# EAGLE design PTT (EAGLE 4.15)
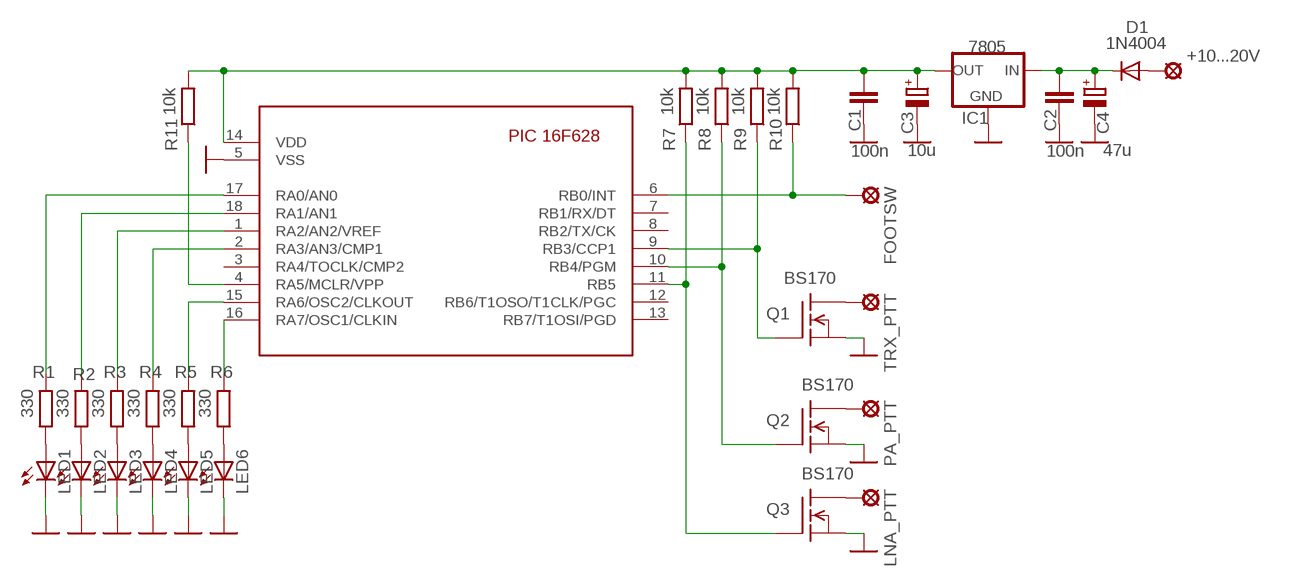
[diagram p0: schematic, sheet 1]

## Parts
+10...20V  MCS08  [MCS08]
C1  100n  C-EU050-025X075  [C050-025X075]
C2  100n  C-EU050-025X075  [C050-025X075]
C3  10u  CPOL-EUB45181C  [B45181C]
C4  47u  CPOL-EUB45181C  [B45181C]
D1  1N4004  [DO41-10]
FOOTSW  MCS08  [MCS08]
IC1  7805  78XXS  [78XXS]
LED1  LED3MM  [LED3MM]
LED2  LED3MM  [LED3MM]
LED3  LED3MM  [LED3MM]
LED4  LED3MM  [LED3MM]
LED5  LED3MM  [LED3MM]
LED6  LED3MM  [LED3MM]
LNA_PTT  MCS08  [MCS08]
PA_PTT  MCS08  [MCS08]
Q1  BS170  BSS296  [TO92]
Q2  BS170  BSS296  [TO92]
Q3  BS170  BSS296  [TO92]
R1  330  R-EU_0204/7  [0204/7]
R2  330  R-EU_0204/7  [0204/7]
R3  330  R-EU_0204/7  [0204/7]
R4  330  R-EU_0204/7  [0204/7]
R5  330  R-EU_0204/7  [0204/7]
R6  330  R-EU_0204/7  [0204/7]
R7  10k  R-EU_0204/7  [0204/7]
R8  10k  R-EU_0204/7  [0204/7]
R9  10k  R-EU_0204/7  [0204/7]
R10  10k  R-EU_0204/7  [0204/7]
R11  10k  R-EU_0204/7  [0204/7]
TRX_PTT  MCS08  [MCS08]
U$1  16F628  [PIC16F628-18-LEAD-PDIP]

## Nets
GND: C1.2 C2.2 C3.- C4.- IC1.GND LED1.K(C) LED2.K(C) LED3.K(C) LED4.K(C) LED5.K(C) LED6.K(C) Q1.3(S) Q2.3(S) Q3.3(S) U$1.5(VSS)
N$1: R1.2 U$1.17(RA0/AN0)
N$2: LED1.A R1.1
N$3: R2.2 U$1.18(RA1/AN1)
N$4: LED2.A R2.1
N$5: R3.2 U$1.1(RA2/AN2/VREF)
N$6: LED3.A R3.1
N$7: R4.2 U$1.2(RA3/AN3/CMP1)
N$8: LED4.A R4.1
N$9: R5.2 U$1.15(RA6/OSC2/CLKOUT)
N$10: LED5.A R5.1
N$11: R6.2 U$1.16(RA7/OSC1/CLKIN)
N$12: LED6.A R6.1
N$13: FOOTSW.MP R10.1 U$1.6(RB0/INT)
N$14: R11.1 U$1.4(RA5/MCLR/VPP)
N$15: C1.1 C3.+ IC1.OUT R7.2 R8.2 R9.2 R10.2 R11.2 U$1.14(VDD)
N$16: Q1.1(G) R9.1 U$1.9(RB3/CCP1)
N$17: Q2.1(G) R8.1 U$1.10(RB4/PGM)
N$18: Q3.1(G) R7.1 U$1.11(RB5)
N$19: Q1.2(D) TRX_PTT.MP
N$20: PA_PTT.MP Q2.2(D)
N$21: LNA_PTT.MP Q3.2(D)
N$22: C2.1 C4.+ D1.C IC1.IN
N$23: +10...20V.MP D1.A
Unconnected: U$1.3(RA4/TOCLK/CMP2) U$1.7(RB1/RX/DT) U$1.8(RB2/TX/CK) U$1.12(RB6/T1OSO/T1CLK/PGC) U$1.13(RB7/T1OSI/PGD)

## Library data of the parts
+10...20V FOOTSW LNA_PTT PA_PTT TRX_PTT = solpad:MCS08: SOLDER PAD
C1 C2 = rcl:C-EU: CAPACITOR, European symbol
C3 C4 = rcl:CPOL-EU: POLARIZED CAPACITOR, European symbol
D1 = diode:1N4004: DIODE
IC1 = v-reg:78XXS: VOLTAGE REGULATOR
LED1-LED6 = led:LED: LED
Q1-Q3 = transistor-fet:BSS296: N-Channel Enhancement MOSFET not checked
R1-R11 = rcl:R-EU_: RESISTOR, European symbol
U$1 = pic16f6xx:16F628: Microchip component PIC 16F628 Eric Magraner - eric_magraner@yahoo.fr 03/2004

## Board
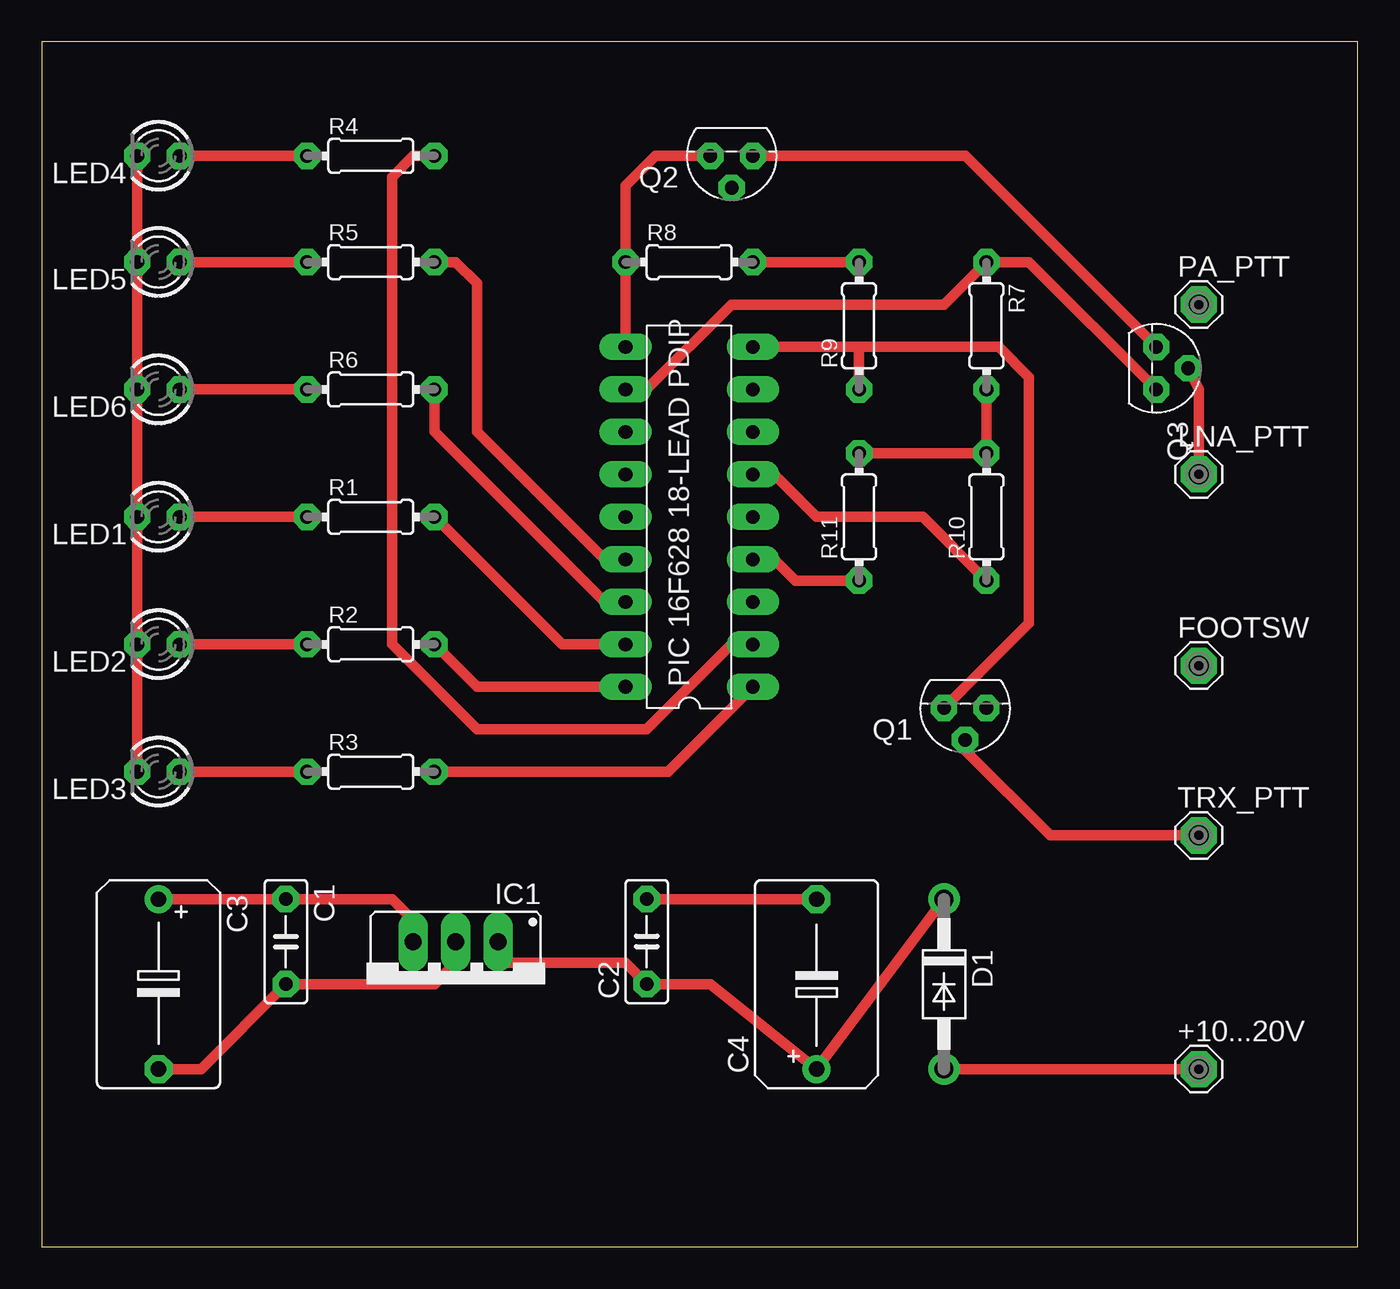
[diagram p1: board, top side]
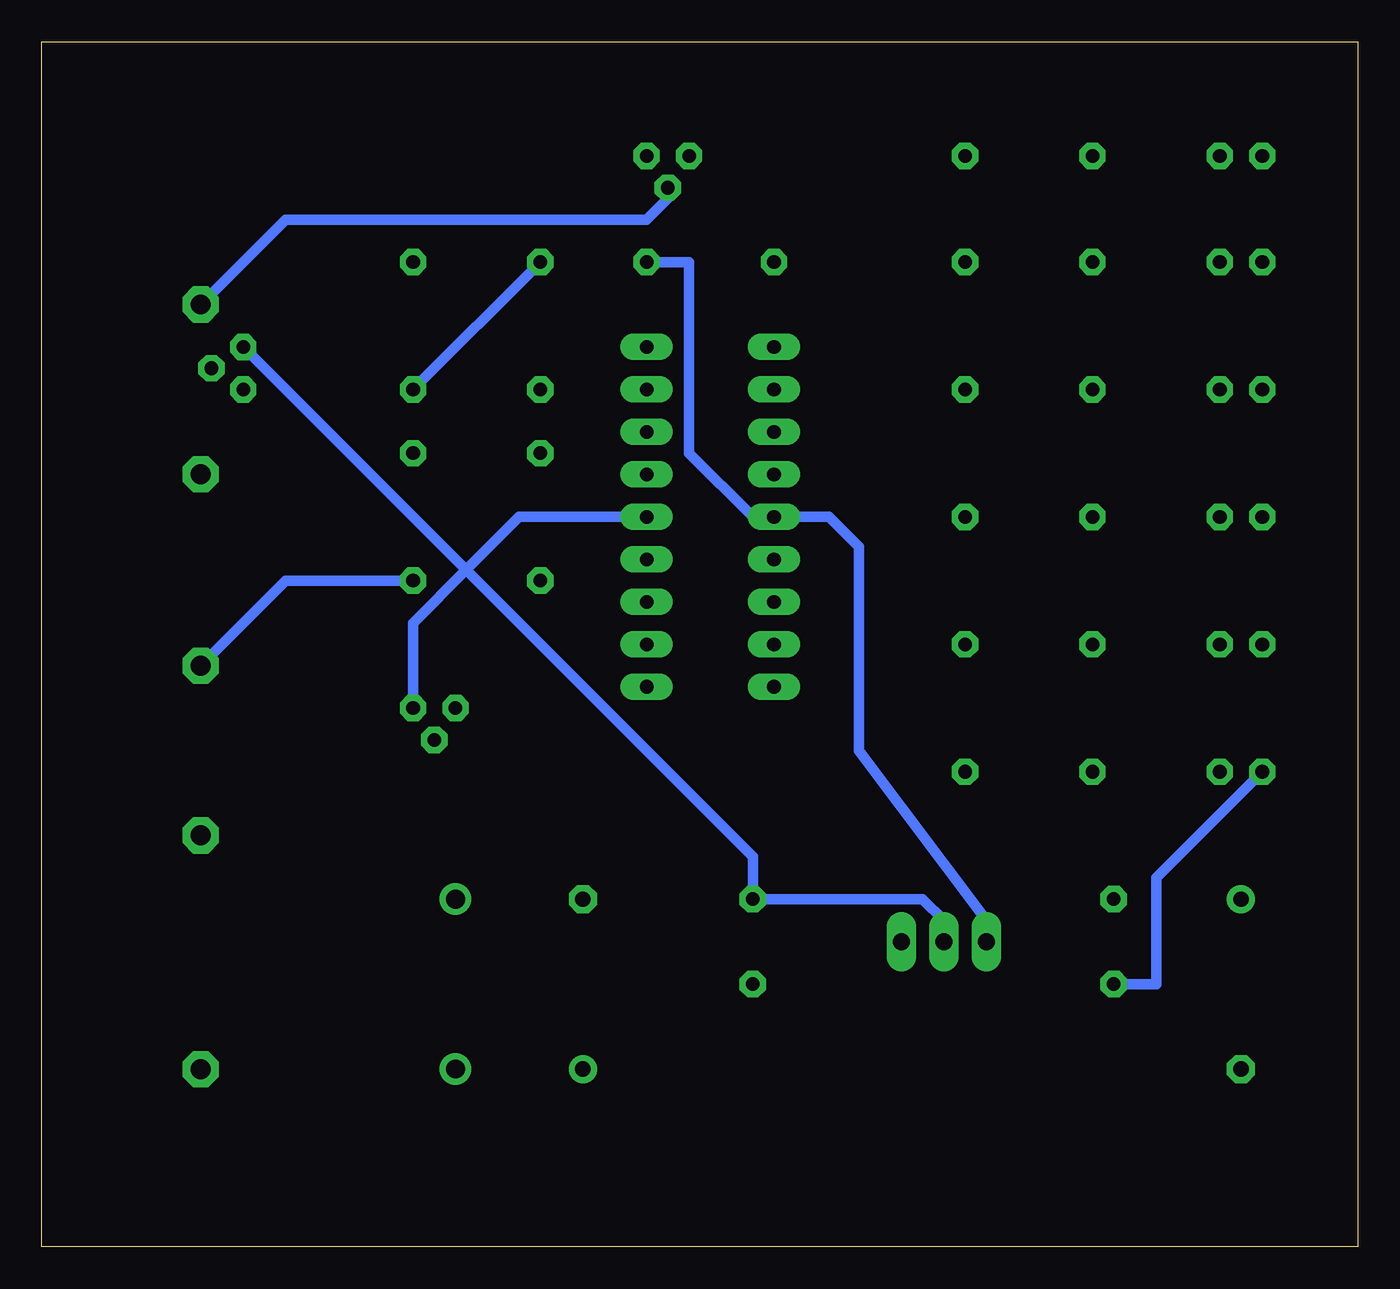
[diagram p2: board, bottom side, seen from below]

Size 78.72 x 72.06 mm. Coordinates in mm from the lower left corner, seen from the top.
Outline: 0,0 78.72,0 78.72,72.06 0,72.06 0,0
Copper layers (1*16): Top 0.035mm / dielectric 1.5mm / Bottom 0.035mm
Design rules "default": minimum track width 25mil, minimum drill 30mil, track to track 8mil, track to pad 8mil, pad to pad 8mil, via to via 8mil, smd to smd 8mil, copper to edge 40mil, drill to drill 8mil, minimum pad ring 15mil, minimum via ring 8mil, stop-mask expansion 4mil, vias tented up to drill 0mil, thermal gap 10mil

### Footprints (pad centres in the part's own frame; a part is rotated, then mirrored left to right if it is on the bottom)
MCS08 = drill 1.194 pad 2.159 octagon: MP 0,0
C050-025X075 = drill 0.813 octagon: 1 -2.54,0; 2 2.54,0
B45181C = drill 0.914 round: + -5.08,0 | drill 0.914 octagon: - 5.08,0
DO41-10 = drill 1.118 round: A 5.08,0; C -5.08,0
78XXS = drill 1.016 long: GND 0,-2.54; IN -2.54,-2.54; OUT 2.54,-2.54
LED3MM = drill 0.813 octagon: A -1.27,0; K 1.27,0
TO92 = drill 0.813 octagon: 1 1.27,0; 2 0,1.905; 3 -1.27,0
0204/7 = drill 0.813 octagon: 1 -3.81,0; 2 3.81,0
PIC16F628-18-LEAD-PDIP = drill 0.813 long: 1 -10.16,-3.81; 2 -7.62,-3.81; 3 -5.08,-3.81; 4 -2.54,-3.81; 5 0,-3.81; 6 2.54,-3.81; 7 5.08,-3.81; 8 7.62,-3.81; 9 10.16,-3.81; 10 10.16,3.81; 11 7.62,3.81; 12 5.08,3.81; 13 2.54,3.81; 14 0,3.81; 15 -2.54,3.81; 16 -5.08,3.81; 17 -7.62,3.81; 18 -10.16,3.81

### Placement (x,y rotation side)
+10...20V  69.21,10.63 0 top
C1  14.6,18.25 270 top
C2  36.19,18.25 90 top
C3  6.98,15.71 270 top
C4  46.35,15.71 90 top
D1  53.97,15.71 270 top
FOOTSW  69.21,34.76 0 top
IC1  24.76,15.71 180 top
LED1  6.98,43.65 180 top
LED2  6.98,36.03 180 top
LED3  6.98,28.41 180 top
LED4  6.98,65.24 180 top
LED5  6.98,58.89 180 top
LED6  6.98,51.27 180 top
LNA_PTT  69.21,46.19 0 top
PA_PTT  69.21,56.35 0 top
Q1  55.24,32.22 180 top
Q2  41.27,65.24 180 top
Q3  66.67,52.54 270 top
R1  19.68,43.65 0 top
R2  19.68,36.03 0 top
R3  19.68,28.41 0 top
R4  19.68,65.24 0 top
R5  19.68,58.89 0 top
R6  19.68,51.27 0 top
R7  56.51,55.08 270 top
R8  38.73,58.89 0 top
R9  48.89,55.08 90 top
R10  56.51,43.65 90 top
R11  48.89,43.65 90 top
TRX_PTT  69.21,24.6 0 top
U$1  38.73,43.65 90 top

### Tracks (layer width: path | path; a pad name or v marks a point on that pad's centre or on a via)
GND
  Top 0.635: Q3.3 55.24,65.24 Q2.3 | LED3.K LED2.K LED1.K LED6.K LED5.K LED4.K | C3.- 9.52,10.63 C1.2 23.49,15.71 24.76,16.98 IC1.GND | C2.2 C4.-
  Bottom 0.635: IC1.GND 24.76,19.52 26.03,20.79 C2.2 36.19,23.33 53.33,40.47 | LED3.K 12.06,22.06 12.06,15.71 C1.2 | Q1.3 56.51,37.3 53.33,40.47 | 53.33,40.47 50.16,43.65 U$1.5 | 53.33,40.47 Q3.3
N$1
  Top 0.635: R1.2 31.11,36.03 U$1.17
N$2
  Top 0.635: LED1.A R1.1
N$3
  Top 0.635: R2.2 26.03,33.49 U$1.18
N$4
  Top 0.635: LED2.A R2.1
N$5
  Top 0.635: R3.2 37.46,28.41 U$1.1
N$6
  Top 0.635: LED3.A R3.1
N$7
  Top 0.635: R4.2 22.22,65.24 20.95,63.97 20.95,36.03 26.03,30.95 36.19,30.95 41.27,36.03 U$1.2
N$8
  Top 0.635: LED4.A R4.1
N$9
  Top 0.635: R5.2 24.76,58.89 26.03,57.62 26.03,48.73 33.65,41.11 U$1.15
N$10
  Top 0.635: LED5.A R5.1
N$11
  Top 0.635: R6.2 23.49,48.73 33.65,38.57 U$1.16
N$12
  Top 0.635: LED6.A R6.1
N$13
  Top 0.635: R10.1 52.7,43.65 46.35,43.65 43.81,46.19 U$1.6
  Bottom 0.635: FOOTSW.MP 64.13,39.84 R10.1
N$14
  Top 0.635: R11.1 45.08,39.84 43.81,41.11 U$1.4
N$15
  Top 0.635: C3.+ C1.1 20.95,20.79 22.22,19.52 IC1.OUT | R11.2 R10.2 R7.2 | R8.2 R9.2
  Bottom 0.635: R8.2 40,58.89 40,47.46 36.19,43.65 U$1.14 31.64,43.65 29.84,41.85 29.84,29.68 22.22,19.52 IC1.OUT | R9.2 R7.2
N$16
  Top 0.635: Q1.1 59.05,37.3 59.05,52.01 57.25,53.81 48.89,53.81 | 48.89,53.81 U$1.9 | 48.89,53.81 R9.1
N$17
  Top 0.635: U$1.10 R8.1 34.92,63.44 36.72,65.24 Q2.1
N$18
  Top 0.635: U$1.11 36.19,51.27 41.27,56.35 53.97,56.35 R7.1 59.05,58.89 Q3.1
N$19
  Top 0.635: TRX_PTT.MP 60.32,24.6 55.24,29.68 Q1.2
N$20
  Bottom 0.635: PA_PTT.MP 64.13,61.43 42.54,61.43 41.27,62.7 Q2.2
N$21
  Top 0.635: LNA_PTT.MP 69.21,51.27 Q3.2
N$22
  Top 0.635: IC1.IN 27.3,16.98 34.92,16.98 C2.1 40,15.71 C4.+ D1.C
N$23
  Top 0.635: D1.A +10...20V.MP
